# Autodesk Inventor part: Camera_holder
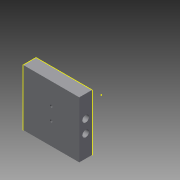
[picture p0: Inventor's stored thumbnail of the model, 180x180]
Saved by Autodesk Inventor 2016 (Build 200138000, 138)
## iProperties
Created: 2014-08
Part Number: Camera_holder
Material: Generic
Document SubType Name: Modeling
Designer: James
Density: 1 g/cm^3
Appearance: Default
Author: James
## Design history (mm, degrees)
sketch "Sketch1"
  geometry: L1 (-48.723, 40.684)-(-40.723, 40.684); L2 (-40.723, 40.684)-(-40.723, 5.684); L3 (-40.723, 5.684)-(-48.723, 5.684); L4 (-48.723, 5.684)-(-48.723, 40.684); L5 (-48.723, 40.684)-(-40.723, 5.684); L6 (-40.723, 40.684)-(-48.723, 5.684); 2 further points
  constraints: 12 end point, 2 midpoint, 2 parallel, 1 horizontal, 1 perpendicular
  dimensions: "d2" = 8 distance between parallel lines of L2 L4; "d3" = 35 distance between parallel lines of L1 L3
extrude "Extrusion1" new body sketch "Sketch1" distance "d0" = 35; taper "d1" = 0 deg
sketch "Sketch5"
  geometry: L1 (0, 0)-(0, 35) reference; L2 (0, 0)-(35, 0) reference; L3 (35, 35)-(35, 0) reference; L4 (0, 35)-(35, 35) reference; C1 r 2.383 at (17.5, 17.5); 6 further points
  constraints: 1 centre point, 1 coincident
  dimensions: "d22" = 21 distance of point (7, 17.5) point (28, 17.5); "d23" = 10.5 distance of point (28, 17.5) point (17.5, 17.5) (= 0.5 x d22); "d24" = 35 distance between parallel lines of L1 L3 (derived); "d25" = 35 distance between parallel lines of L2 L4 (derived); "d26" = 17.5 distance from line of L4 point (17.5, 17.5); "d27" = 17.5 distance from line of L1 point (17.5, 17.5); "d28" = 12.5 distance of point (7, 17.5) point (7, 5); "d29" = 12.5 distance of point (28, 17.5) point (28, 5) (= d28); "d30" = 21 distance of point (7, 5) point (28, 5) (= d22)
hole "Hole2" sketch "Sketch5" at (7, 17.5), (7, 5), (28, 5), (28, 17.5) diameter "d31" = 1.567; stored, may be unused: countersink angle "d35" = 90 deg, drill point angle "d37" = 118 deg; dims "d32" = 6, "d33" = 4, "d34" = 2, "d36" = 5
sketch "Sketch6"
  geometry: L1 (0, 0)-(0, 35) reference; L2 (0, 0)-(35, 0) reference; L3 (35, 35)-(35, 0) reference; L4 (0, 35)-(35, 35) reference; L5 (5, 3)-(30, 3); L6 (30, 3)-(30, 27); L7 (30, 27)-(5, 27); L8 (5, 27)-(5, 3); C1 r 0.784 at (28, 5) reference; C2 r 0.784 at (7, 17.5) reference; C3 r 0.784 at (7, 5) reference; C4 r 0.784 at (28, 17.5) reference; C5 r 2.116 at (17.35, 17.35); 2 further points
  constraints: 8 end point, 2 parallel, 1 centre point, 1 coincident, 1 horizontal, 1 perpendicular
  dimensions: "d38" = 24 distance between parallel lines of L5 L7; "d39" = 25 distance between parallel lines of L6 L8; "d40" = 2 distance from line of C3.centre L8; "d41" = 2 distance from line of L5 C3.centre
sketch "Sketch7"
  geometry: L1 (0, 0)-(0, 35) reference; L2 (0, 0)-(35, 0) reference; L3 (35, 35)-(35, 0) reference; L4 (0, 35)-(35, 35) reference; 5 further points
  dimensions: "d49" = 2.5 distance from line of L1 point (2.5, 2.5); "d50" = 2.5 distance from line of L2 point (2.5, 2.5) (= d49); "d51" = 2.5 distance from line of L4 point (2.5, 32.5) (= d49); "d52" = 2.5 distance from line of L1 point (2.5, 32.5) (= d49); "d53" = 2.5 distance from line of L4 point (32.5, 32.5) (= d49); "d54" = 2.5 distance from line of L3 point (32.5, 32.5) (= d49); "d55" = 2.5 distance from line of L2 point (32.5, 2.5) (= d49); "d56" = 2.5 distance from line of L3 point (32.5, 2.5) (= d49)
hole "Hole3" sketch "Sketch7" at (2.5, 32.5), (2.5, 2.5), (32.5, 2.5), (32.5, 32.5) diameter "d42" = 2.013; stored, may be unused: countersink angle "d46" = 90 deg, drill point angle "d48" = 118 deg; dims "d43" = 6, "d44" = 4, "d45" = 2, "d47" = 5
sketch "Sketch13"
  geometry: L1 (40.684, -48.723)-(40.684, -40.723) reference; L2 (40.684, -40.723)-(5.684, -40.723) reference; 3 further points
  dimensions: "d90" = 13.5 distance from line of L1 point (27.184, -44.723); "d91" = 8 distance of point (27.184, -44.723) point (19.184, -44.723); "d103" = 4 distance from line of L2 point (19.184, -44.723); "d104" = 4 distance from line of point (27.184, -44.723) L2 (= d103)
hole "Hole7" sketch "Sketch13" at (19.184, -44.723), (27.184, -44.723) diameter "d94" = 4.1; stored, may be unused: countersink angle "d98" = 90 deg, drill point angle "d100" = 118 deg; dims "d95" = 6, "d96" = 4, "d97" = 2, "d99" = 4.1
sketch "Sketch15"
  geometry: L1 (40.684, -48.723)-(40.684, -40.723) reference; L2 (40.684, -40.723)-(5.684, -40.723) reference; L3 (5.684, -40.723)-(5.684, -48.723) reference; L4 (5.684, -48.723)-(40.684, -48.723) reference; C1 r 2.05 at (19.184, -44.723) reference; C2 r 2.05 at (27.184, -44.723) reference; 1 further point
sketch "Sketch16"
  geometry: L1 (35, 35)-(35, 0) reference; L2 (35, 23.55)-(35, 19.45) reference; L3 (35, 21.5)-(0, 21.5); L4 (0, 0)-(0, 35) reference; L5 (0, 19.45)-(0, 23.55) reference; L6 (35, 15.55)-(35, 11.45) reference; L7 (35, 13.5)-(0, 13.5); L8 (0, 11.45)-(0, 15.55) reference; 3 further points
  constraints: 6 midpoint, 4 end point, 2 point on line
hole "Hole8" sketch "Sketch16" at (17.5, 21.5), (17.5, 13.5) diameter "d105" = 1.567; stored, may be unused: countersink angle "d109" = 90 deg, drill point angle "d111" = 118 deg; dims "d106" = 4, "d107" = 4, "d108" = 2, "d110" = 3
body "Solid1"
